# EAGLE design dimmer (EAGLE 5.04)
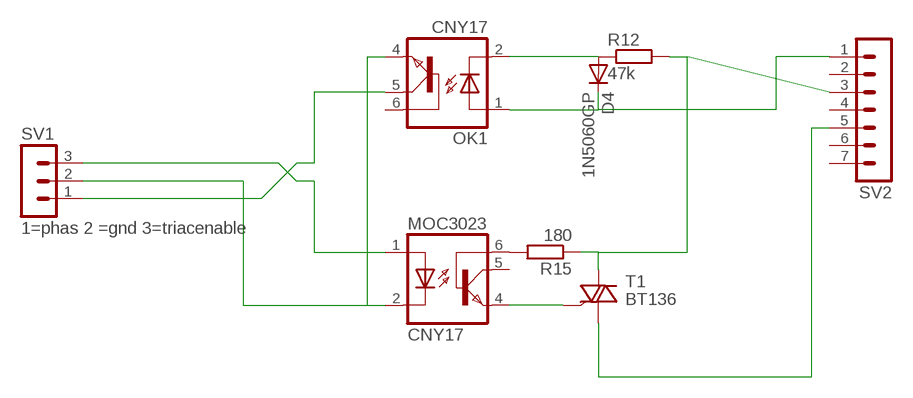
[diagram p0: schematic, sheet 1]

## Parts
D4  1N5060GP  [DO15-12]
MOC3023  CNY17  [DIL06]
OK1  CNY17  [DIL06]
R12  47k  R-EU_0617/22  [0617/22]
R15  180  R-EU_0204/7  [0204/7]
SV1  1=phas 2 =gnd 3=triacenable  MA03-1  [MA03-1]
SV2  MA07-1  [MA07-1]
T1  BT136  [TO220AB]

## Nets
N$1: OK1.5(COL) SV1.1
N$2: MOC3023.2(C) OK1.4(EMI) SV1.2
N$3: MOC3023.1(A) SV1.3
N$35 [220]: D4.A OK1.2(C) R12.1
N$36 [220]: D4.C OK1.1(A) SV2.1
N$39 [220]: MOC3023.4(EMI) T1.3(G)
N$40: MOC3023.6(BAS) R15.2
N$41 [220]: R12.2 R15.1 SV2.3 T1.2(A2)
N$42 [220]: SV2.5 T1.1(A1)
Unconnected: MOC3023.5(COL) OK1.6(BAS) SV2.2 SV2.4 SV2.6 SV2.7

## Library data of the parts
D4 = diode:1N5060GP: DIODE
MOC3023 OK1 = optocoupler:CNY17: SIEMENS OPTO COUPLER
R12 R15 = resistor:R-EU_: RESISTOR, European symbol
SV1 = con-lstb:MA03-1: PIN HEADER
SV2 = con-lstb:MA07-1: PIN HEADER
T1 = triac:BT136: Triac BT136 series E sensitive gate Source: http://www.nxp.com/acrobat_download/datasheets/BT136_SERIES_E_2.pdf

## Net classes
0 default: width 0.508 mm, clearance 0.254 mm
1 220: width 0.762 mm, clearance 0.762 mm

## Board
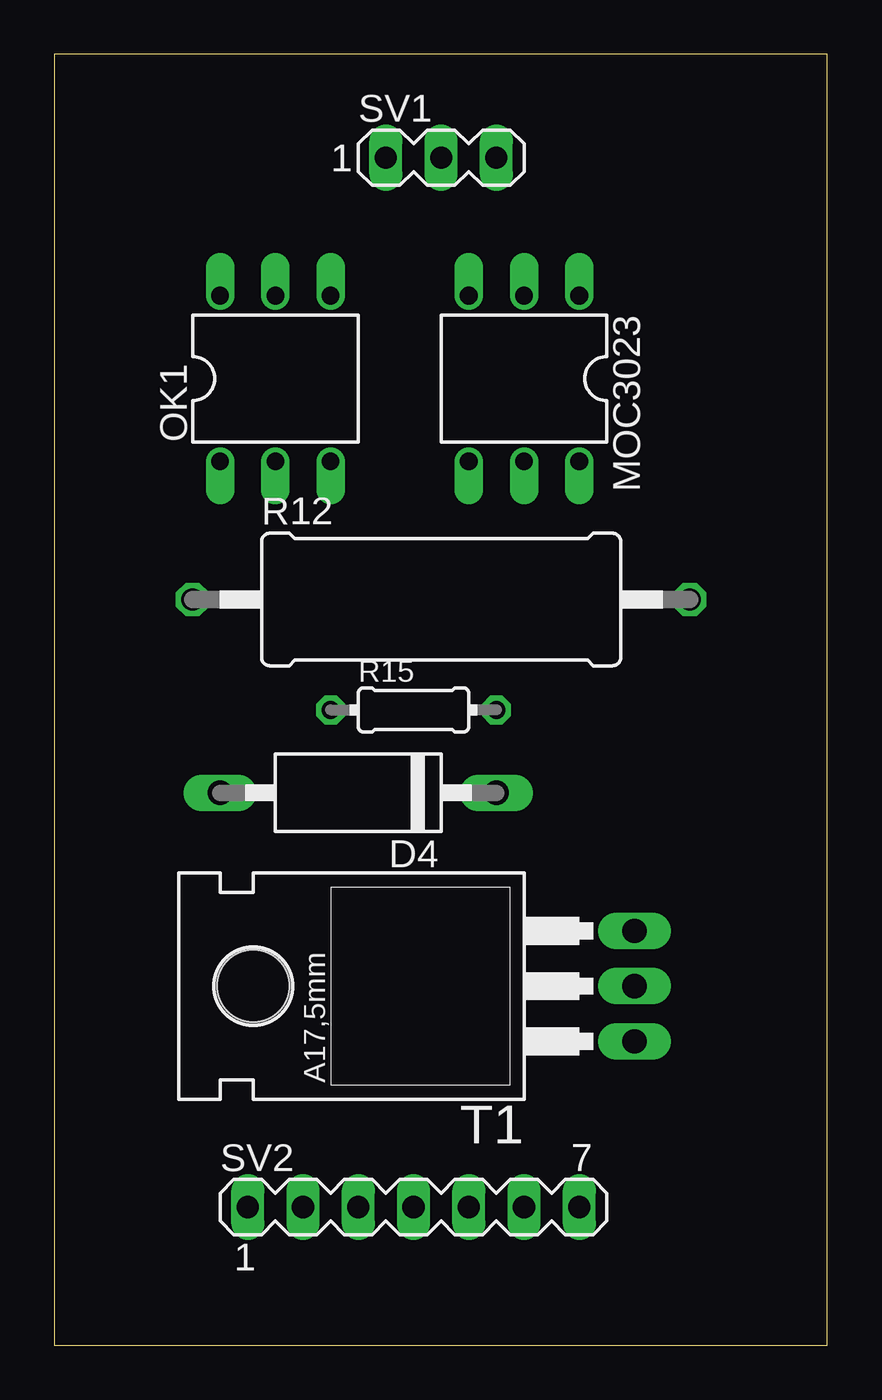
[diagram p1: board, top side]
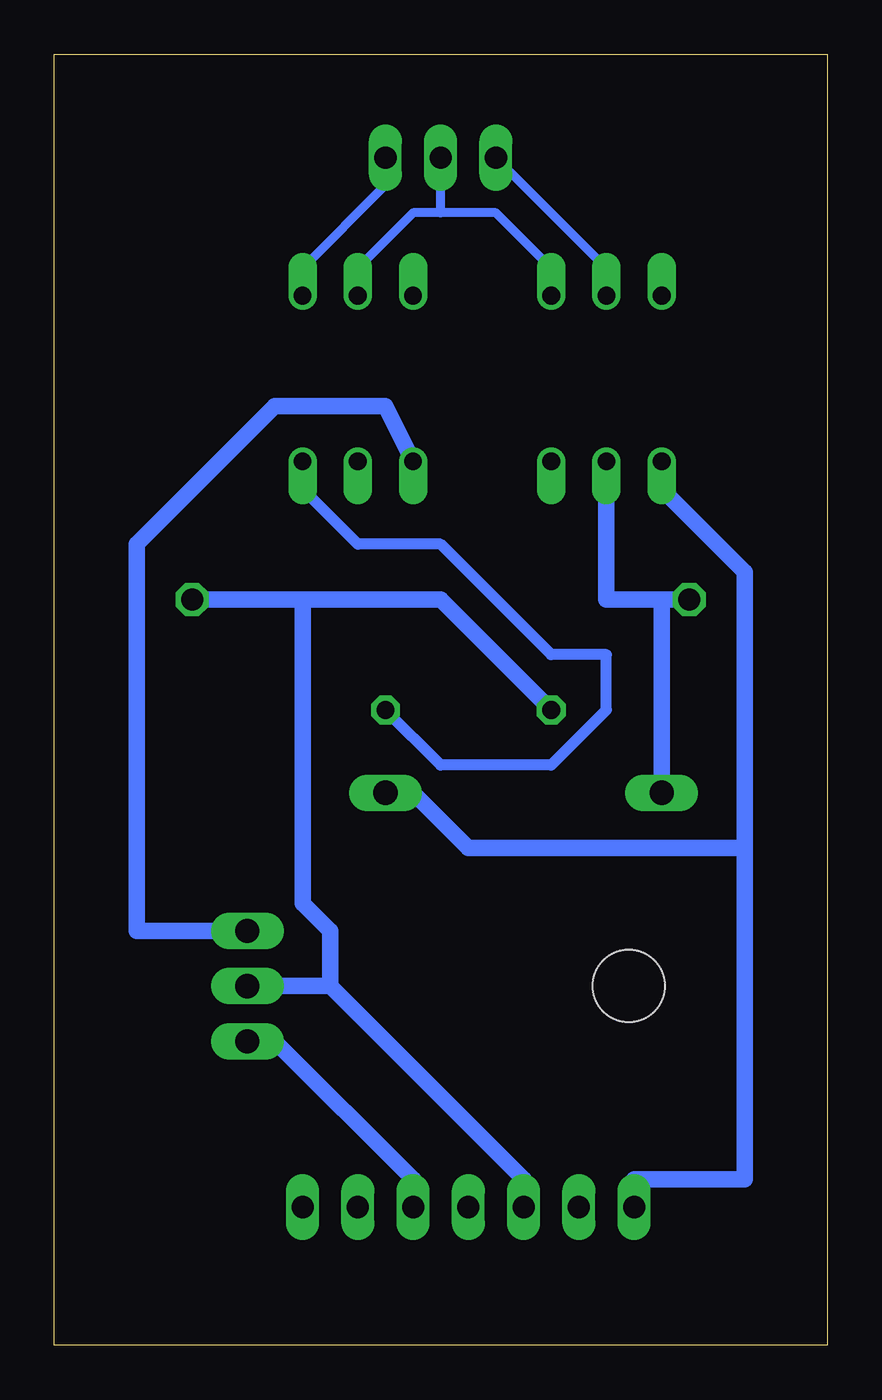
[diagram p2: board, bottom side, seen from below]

Size 35.54 x 59.36 mm. Coordinates in mm from the lower left corner, seen from the top.
Outline: 0,0 35.54,0 35.54,59.36 0,59.36 0,0
Copper layers (1*16): Top 0.035mm / dielectric 1.5mm / Bottom 0.035mm
Design rules "default": minimum track width 10mil, minimum drill 24mil, track to track 8mil, track to pad 8mil, pad to pad 8mil, via to via 8mil, smd to smd 8mil, copper to edge 40mil, drill to drill 8mil, minimum pad ring 10mil, minimum via ring 8mil, stop-mask expansion 4mil, vias tented up to drill 0mil, thermal gap 10mil

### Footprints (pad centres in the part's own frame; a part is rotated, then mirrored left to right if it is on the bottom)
DO15-12 = drill 1.118 long: A 6.35,0; C -6.35,0
DIL06 = drill 0.813 offset: 1 -2.54,-3.81; 2 0,-3.81; 3 2.54,-3.81; 4 2.54,3.81; 5 0,3.81; 6 -2.54,3.81
0617/22 = drill 1.016 octagon: 1 -11.43,0; 2 11.43,0
0204/7 = drill 0.813 octagon: 1 -3.81,0; 2 3.81,0
MA03-1 = drill 1.016 long: 1 -2.54,0; 2 0,0; 3 2.54,0
MA07-1 = drill 1.016 long: 1 -7.62,0; 2 -5.08,0; 3 -2.54,0; 4 0,0; 5 2.54,0; 6 5.08,0; 7 7.62,0
TO220AB = drill 1.118 long: 1 -2.54,-6.35; 2 0,-6.35; 3 2.54,-6.35 | hole 3.302: 0,11.176

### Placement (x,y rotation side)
D4  13.97,25.4 180 top
MOC3023  21.59,44.45 180 top
OK1  10.16,44.45 0 top
R12  17.78,34.29 0 top
R15  16.51,29.21 0 top
SV1  17.78,54.61 0 top
SV2  16.51,6.35 0 top
T1  20.32,16.51 90 top

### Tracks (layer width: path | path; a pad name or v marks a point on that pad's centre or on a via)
N$1
  Bottom 0.406: SV1.1 10.16,49.53 OK1.5
N$2
  Bottom 0.406: 17.78,52.07 SV1.2 | 17.78,52.07 19.05,52.07 21.59,49.53 | 17.78,52.07 15.24,52.07 12.7,49.53 OK1.4
  Bottom 0.508: 21.59,49.53 MOC3023.2
N$3
  Bottom 0.406: SV1.3 20.32,53.34 24.13,49.53 MOC3023.1
N$35
  Bottom 0.762: 7.62,34.29 R12.1 | 7.62,34.29 10.16,34.29 OK1.2 | D4.A 7.62,34.29
N$36
  Bottom 0.762: 3.81,22.86 3.81,7.62 8.89,7.62 SV2.1 | 3.81,22.86 3.81,35.56 7.62,39.37 OK1.1 | 3.81,22.86 16.51,22.86 19.05,25.4 D4.C
N$39
  Bottom 0.762: MOC3023.4 20.32,43.18 25.4,43.18 31.75,36.83 31.75,19.05 T1.3
N$40
  Bottom 0.508: R15.2 17.78,26.67 12.7,26.67 10.16,29.21 10.16,31.75 12.7,31.75 17.78,36.83 21.59,36.83 24.13,39.37 MOC3023.6
N$41
  Bottom 0.762: R15.1 17.78,34.29 24.13,34.29 | 24.13,34.29 R12.2 | 22.86,16.51 13.97,7.62 SV2.3 | 22.86,16.51 T1.2 | 24.13,34.29 24.13,20.32 22.86,19.05 22.86,16.51
N$42
  Bottom 0.762: SV2.5 19.05,7.62 25.4,13.97 T1.1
